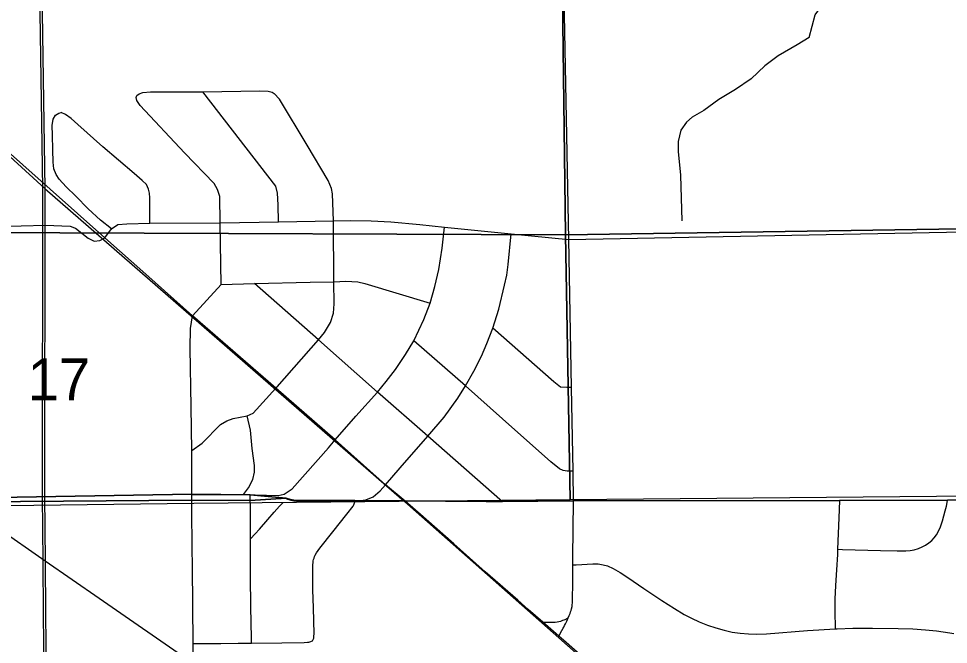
# Model space of a CAD drawing. Extents: x 0 to 40.2, y 0 to 22.
# Drawn here: x 4.597 to 5.526, y 17.276 to 17.901 of the extents above; entities that cross this region are included whole.
import ezdxf

# ---------------------------------------------------------------- set-up
doc = ezdxf.new("R2010")
doc.units = 0
for name, color, linetype in [('GM_X_City_Street', 7, 'Continuous'), ('GM_X_Corporation', 7, 'Continuous'), ('GM_X_Major_Lake', 7, 'Continuous'), ('GM_X_Major_Lake_Text', 7, 'Continuous'), ('GM_X_Major_River', 7, 'Continuous'), ('GM_X_Minor_Lake', 7, 'Continuous'), ('GM_X_Rail_Line', 7, 'Continuous'), ('GM_X_Unincorporated_Location', 7, 'Continuous')]:
    doc.layers.add(name, color=color, linetype=linetype)

msp = doc.modelspace()

# ---------------------------------------------------------------- linework, layer by layer
at = {"layer": 'GM_X_Corporation'}
for points in [[(5.1306, 18.69122), (6.13405, 18.70621), (6.1533, 17.70056), (5.14342, 17.68519)], [(5.1306, 18.69122), (5.14342, 17.68519), (4.13231, 17.68919), (4.11898, 18.68419)], [(6.1533, 17.70056), (6.15543, 17.42907), (5.77027, 17.42591), (5.14797, 17.42035), (5.14342, 17.68519)], [(5.14342, 17.68519), (5.14797, 17.42035), (4.77185, 17.41656), (4.13209, 17.4086), (4.13231, 17.68919)]]:
    msp.add_lwpolyline(points, close=True, dxfattribs=at)
for points in [[(4.12897, 17.41484), (4.76975, 17.42604), (4.82809, 17.4251), (4.8643, 17.42185), (4.86853, 17.42044), (4.87173, 17.41985), (4.87659, 17.41944), (4.88705, 17.4194), (4.91747, 17.41952), (4.93294, 17.41943), (4.98282, 17.41931), (5.0642, 17.41862), (5.08033, 17.4187), (5.15118, 17.41905), (5.41736, 17.41969), (5.5251, 17.41995), (5.58951, 17.42013), (5.59895, 17.42023), (5.60684, 17.42043), (5.61622, 17.42043), (5.63231, 17.42055), (6.1544, 17.42475), (6.56089, 17.42856)], [(6.56089, 17.42856), (6.1544, 17.42475), (5.63231, 17.42055), (5.61622, 17.42043), (5.60684, 17.42043), (5.59895, 17.42023), (5.58951, 17.42013), (5.5251, 17.41995), (5.41736, 17.41969), (5.15118, 17.41905), (5.08033, 17.4187), (5.0642, 17.41862), (4.98282, 17.41931), (4.93294, 17.41943), (4.91747, 17.41952), (4.88705, 17.4194), (4.87659, 17.41944), (4.87173, 17.41985), (4.86853, 17.42044), (4.8643, 17.42185), (4.82809, 17.4251), (4.76975, 17.42604), (4.12897, 17.41484)], [(6.56089, 17.42856), (6.1544, 17.42475), (5.63231, 17.42055), (5.61622, 17.42043), (5.60684, 17.42043), (5.59895, 17.42023), (5.58951, 17.42013), (5.5251, 17.41995), (5.41736, 17.41969), (5.15118, 17.41905), (5.0642, 17.41862), (4.98282, 17.41931), (4.93294, 17.41943), (4.91747, 17.41952), (4.88705, 17.4194), (4.87659, 17.41944), (4.87173, 17.41985), (4.86853, 17.42044), (4.8643, 17.42185), (4.8283, 17.41938), (4.76962, 17.4198), (4.12897, 17.41484)], [(4.12897, 17.41484), (4.76962, 17.4198), (4.8283, 17.41938), (4.8643, 17.42185), (4.86853, 17.42044), (4.87173, 17.41985), (4.87659, 17.41944), (4.88705, 17.4194), (4.91747, 17.41952), (4.93294, 17.41943), (4.98282, 17.41931), (5.0642, 17.41862), (5.15118, 17.41905), (5.41736, 17.41969), (5.5251, 17.41995), (5.58951, 17.42013), (5.59895, 17.42023), (5.60684, 17.42043), (5.61622, 17.42043), (5.63231, 17.42055), (6.1544, 17.42475), (6.56089, 17.42856)], [(6.56089, 17.42856), (6.1544, 17.42475), (5.63231, 17.42055), (5.61622, 17.42043), (5.60684, 17.42043), (5.59895, 17.42023), (5.58951, 17.42013), (5.5251, 17.41995), (5.41736, 17.41969), (5.15118, 17.41905), (5.08033, 17.4187), (5.0642, 17.41862), (4.98282, 17.41931), (4.93294, 17.41943), (4.91747, 17.41952), (4.88705, 17.4194), (4.87659, 17.41944), (4.87173, 17.41985), (4.86853, 17.42044), (4.8643, 17.42185), (4.82809, 17.4251), (4.76975, 17.42604), (4.12897, 17.41484)], [(4.12897, 17.41484), (4.76975, 17.42604), (4.82809, 17.4251), (4.8643, 17.42185), (4.86853, 17.42044), (4.87173, 17.41985), (4.87659, 17.41944), (4.88705, 17.4194), (4.91747, 17.41952), (4.93294, 17.41943), (4.98282, 17.41931), (5.0642, 17.41862), (5.08033, 17.4187), (5.15118, 17.41905), (5.41736, 17.41969), (5.5251, 17.41995), (5.58951, 17.42013), (5.59895, 17.42023), (5.60684, 17.42043), (5.61622, 17.42043), (5.63231, 17.42055), (6.1544, 17.42475), (6.56089, 17.42856)]]:
    msp.add_lwpolyline(points, dxfattribs=at)
at = {"layer": 'GM_X_Major_Lake'}
for points in [[(4.72382, 17.64572), (4.68301, 17.68221), (4.57325, 17.7794)], [(4.98304, 17.41876), (4.96348, 17.4352), (4.91301, 17.48009), (4.85393, 17.53179), (4.77045, 17.60402), (4.72382, 17.64572)], [(5.09568, 17.31984), (5.06325, 17.34832), (5.03165, 17.37638), (4.99837, 17.4054), (4.98304, 17.41876)], [(5.19169, 17.23518), (5.16328, 17.26059), (5.14142, 17.27994), (5.13684, 17.28392), (5.12082, 17.29787), (5.10624, 17.31056), (5.09568, 17.31984)]]:
    msp.add_lwpolyline(points, dxfattribs=at)
at = {"layer": 'GM_X_Major_Lake_Text'}
msp.add_line((5.14656, 17.68066), (5.137, 18.18327), dxfattribs=at)
for points in [[(4.09028, 17.68845), (4.1262, 17.68864), (4.1362, 17.68869), (4.25949, 17.68972), (4.37295, 17.69138), (4.46398, 17.69249), (4.48547, 17.69249), (4.53732, 17.69332), (4.56687, 17.69399), (4.5993, 17.69431), (4.62352, 17.69484), (4.64844, 17.69398), (4.65259, 17.69213)], [(4.68301, 17.68221), (4.68968, 17.6911), (4.69585, 17.69546), (4.70491, 17.69603), (4.72792, 17.69668), (4.79825, 17.69727), (4.85669, 17.69826), (4.91151, 17.69908), (4.92838, 17.69941), (4.94904, 17.699), (4.9688, 17.69801), (4.99785, 17.69546), (5.0223, 17.69287), (5.0892, 17.68626), (5.14656, 17.68066)], [(4.65259, 17.69213), (4.65363, 17.69167), (4.66639, 17.68179), (4.6724, 17.67867), (4.67783, 17.67965), (4.68301, 17.68221)], [(5.15141, 17.4185), (5.15117, 17.44883), (5.14952, 17.53243), (5.14656, 17.68066)], [(4.76998, 17.42548), (4.76998, 17.46955), (4.76917, 17.51332), (4.76837, 17.57181), (4.76844, 17.59165), (4.77045, 17.60402)], [(5.15066, 17.35511), (5.15057, 17.36291), (5.15141, 17.4185)], [(5.14611, 17.30224), (5.14716, 17.30467), (5.1479, 17.30662), (5.14853, 17.30825), (5.14897, 17.30949), (5.14953, 17.31137), (5.14998, 17.31355), (5.15012, 17.31478), (5.15038, 17.3177), (5.15052, 17.31953), (5.15051, 17.32113), (5.15051, 17.32274), (5.15051, 17.32457), (5.15063, 17.33322), (5.15076, 17.34713), (5.15066, 17.35511)], [(5.12082, 17.29787), (5.12499, 17.29775), (5.13021, 17.29788), (5.13203, 17.29794), (5.13317, 17.29801), (5.13492, 17.29819), (5.13681, 17.29851), (5.13863, 17.29895), (5.13943, 17.29924), (5.14021, 17.29952), (5.14086, 17.29978), (5.14217, 17.30032), (5.14297, 17.30065), (5.14611, 17.30224)], [(5.13684, 17.28392), (5.13985, 17.28954), (5.14112, 17.29193), (5.14172, 17.29304), (5.14244, 17.29441), (5.14347, 17.29637), (5.14474, 17.29904), (5.14611, 17.30224)]]:
    msp.add_lwpolyline(points, dxfattribs=at)
at = {"layer": 'GM_X_Major_River'}
for p, q in [((4.623, 17.73159), (4.97994, 17.42091)), ((4.54301, 17.4149), (4.62333, 17.35928))]:
    msp.add_line(p, q, dxfattribs=at)
for points in [[(4.62062, 17.42396), (4.6209, 17.73102), (4.61457, 18.14987), (4.61044, 19.18179), (4.60713, 19.57767), (4.60713, 19.63326), (4.61046, 19.67322), (4.61795, 19.71401)], [(4.62295, 17.42396), (4.62323, 17.73104), (4.6169, 18.1499), (4.61277, 19.18181), (4.60946, 19.57768), (4.60946, 19.63316), (4.61277, 19.67292), (4.62022, 19.7135)], [(4.623, 17.73159), (4.52561, 17.82001), (4.4278, 17.90731), (4.17647, 18.13451), (4.06677, 18.21824)], [(4.59498, 15.70159), (4.59656, 15.70372), (4.61052, 15.72266), (4.61811, 15.7396), (4.62426, 15.75717), (4.63093, 15.78112), (4.63373, 15.80092), (4.63465, 15.82821), (4.6339, 15.96965), (4.63233, 16.10669), (4.63064, 16.45685), (4.62545, 16.84695), (4.62537, 16.96937), (4.62178, 17.30668), (4.62122, 17.3587), (4.62062, 17.42396)], [(4.59686, 15.70021), (4.59843, 15.70234), (4.61254, 15.72149), (4.62028, 15.73875), (4.62648, 15.75648), (4.63322, 15.78065), (4.63606, 15.80072), (4.63698, 15.82818), (4.63623, 15.96967), (4.63466, 16.10671), (4.63297, 16.45687), (4.62777, 16.84697), (4.62769, 16.96938), (4.62411, 17.3067), (4.62355, 17.35873), (4.62295, 17.42396)], [(4.97994, 17.42091), (5.30245, 17.13578), (5.95038, 16.5554), (6.62714, 15.93274), (7.15702, 15.44764), (7.76806, 14.87866), (8.24495, 14.44186), (8.61841, 14.1)], [(4.62333, 17.35928), (4.67721, 17.32197), (4.76914, 17.2583), (4.77303, 16.83719)]]:
    msp.add_lwpolyline(points, dxfattribs=at)
at = {"layer": 'GM_X_Minor_Lake'}
for points in [[(5.38688, 17.88245), (5.39001, 17.8938), (5.39276, 17.90516), (5.4035, 17.92023), (5.41194, 17.93343), (5.42123, 17.95611), (5.42217, 17.9762), (5.42117, 17.99063), (5.42501, 17.99704), (5.43046, 18.01255), (5.4298, 18.02317), (5.42952, 18.0338), (5.4315, 18.04402), (5.43575, 18.05347), (5.43737, 18.06483), (5.44013, 18.07657), (5.44328, 18.0902), (5.44756, 18.10268), (5.45976, 18.11319), (5.46588, 18.12034), (5.47465, 18.12746), (5.48037, 18.13234), (5.48574, 18.13988), (5.48957, 18.14592)], [(5.38688, 17.88245), (5.37508, 17.87497), (5.35606, 17.86415), (5.34273, 17.85403), (5.32899, 17.84126), (5.31338, 17.8304), (5.29664, 17.82031), (5.28179, 17.80945), (5.26999, 17.80273), (5.26427, 17.79785), (5.25853, 17.78993), (5.25615, 17.77857), (5.25605, 17.76833), (5.25849, 17.74479), (5.25958, 17.69926)]]:
    msp.add_lwpolyline(points, dxfattribs=at)
at = {"layer": 'GM_X_Rail_Line'}
for points in [[(4.77126, 17.27642), (4.77055, 17.3533), (4.77038, 17.37255), (4.76983, 17.40978), (4.76998, 17.42548)], [(5.15066, 17.35511), (5.15414, 17.35532), (5.1706, 17.35632), (5.17592, 17.35607), (5.181, 17.35533), (5.18544, 17.35407), (5.19097, 17.35144), (5.19793, 17.34744), (5.20577, 17.34245), (5.22172, 17.33166), (5.2398, 17.3195), (5.25243, 17.3115), (5.26206, 17.30572), (5.26921, 17.30187), (5.27715, 17.29815), (5.28528, 17.2949), (5.29358, 17.2921), (5.30202, 17.28977), (5.30998, 17.28806), (5.31803, 17.28682), (5.32614, 17.28609), (5.33428, 17.28591), (5.34426, 17.28629), (5.3852, 17.28947), (5.41327, 17.29118)], [(5.41327, 17.29118), (5.41497, 17.29129), (5.43048, 17.2918), (5.45036, 17.29192), (5.47582, 17.2917), (5.4907, 17.29118), (5.50305, 17.29028), (5.51415, 17.28907), (5.52764, 17.28711), (5.53163, 17.28641)], [(4.77188, 17.22524), (4.77148, 17.25458), (4.77126, 17.27642)]]:
    msp.add_lwpolyline(points, dxfattribs=at)
at = {"layer": 'GM_X_Unincorporated_Location'}
for points in [[(4.71511, 17.82448), (4.71727, 17.82629), (4.72086, 17.82761), (4.72873, 17.82798), (4.78089, 17.8282), (4.83784, 17.82908), (4.84611, 17.82889), (4.85013, 17.82772), (4.85233, 17.82658)], [(4.85669, 17.69826), (4.85614, 17.71506), (4.8554, 17.72678), (4.85372, 17.73366), (4.78089, 17.8282)], [(4.85526, 17.53331), (4.89661, 17.58022), (4.90245, 17.58738), (4.90838, 17.59759), (4.91159, 17.60697), (4.91217, 17.61603), (4.91191, 17.63815), (4.91151, 17.69908), (4.9106, 17.726), (4.90945, 17.73159), (4.90624, 17.73958), (4.88533, 17.77489), (4.85768, 17.8209), (4.85233, 17.82658)], [(4.77045, 17.60402), (4.79928, 17.6356), (4.79825, 17.69727), (4.7979, 17.72345), (4.79567, 17.7304), (4.79226, 17.73657), (4.76274, 17.76727), (4.71839, 17.81437), (4.71479, 17.81945), (4.71427, 17.82249), (4.71511, 17.82448)], [(4.68968, 17.6911), (4.67852, 17.6998), (4.66625, 17.7113), (4.65392, 17.7237), (4.64444, 17.73326), (4.63741, 17.74094), (4.63423, 17.74537), (4.63207, 17.75115), (4.63123, 17.75785), (4.63093, 17.77022), (4.63057, 17.78497), (4.63042, 17.79445), (4.63123, 17.80075), (4.63357, 17.80496), (4.63683, 17.80693), (4.63917, 17.80733)], [(4.72792, 17.69668), (4.72796, 17.72231), (4.72752, 17.72674), (4.72657, 17.73091), (4.72456, 17.73541), (4.72039, 17.7394), (4.71226, 17.74647), (4.68104, 17.7733), (4.65582, 17.79533), (4.64938, 17.80148), (4.64364, 17.80561), (4.63917, 17.80733)], [(5.14656, 17.68066), (5.60992, 17.68952), (5.61291, 17.68958), (5.61798, 17.6897), (5.82615, 17.69451), (5.98519, 17.69809), (6.06403, 17.69944), (6.14544, 17.70075), (6.41974, 17.70708), (6.66088, 17.71027), (7.14766, 17.71966), (7.44219, 17.72601), (7.72193, 17.73118), (7.94375, 17.73546), (8.02286, 17.73868), (8.16105, 17.73241), (8.9, 17.74624)], [(4.76998, 17.42548), (4.82144, 17.42541), (4.85614, 17.42446), (4.86229, 17.426), (4.87012, 17.43134), (4.9065, 17.47233), (4.91301, 17.48009), (4.93395, 17.50374), (4.95562, 17.52796), (4.96403, 17.53858), (4.97355, 17.55058), (4.98343, 17.56544), (4.99178, 17.5792), (5.00188, 17.60051), (5.0081, 17.61698), (5.01286, 17.63359), (5.01689, 17.65036), (5.02025, 17.6718), (5.0223, 17.69287)], [(4.93317, 17.41887), (4.94368, 17.42007), (4.95122, 17.42307), (4.95818, 17.42936), (4.96348, 17.4352), (4.97816, 17.45206), (5.00583, 17.48397), (5.02208, 17.503), (5.0357, 17.52182), (5.04331, 17.53404), (5.0518, 17.54897), (5.05941, 17.56369), (5.06483, 17.57635), (5.0709, 17.5919), (5.07684, 17.6109), (5.08233, 17.63491), (5.08474, 17.64472), (5.08621, 17.65548), (5.0892, 17.68626)], [(4.79928, 17.6356), (4.83271, 17.63663), (4.88813, 17.63789), (4.91191, 17.63815), (4.92399, 17.63868), (4.93578, 17.63817), (4.94295, 17.63663), (5.0081, 17.61698)], [(5.08056, 17.41815), (5.00583, 17.48397), (4.95562, 17.52796), (4.89661, 17.58022), (4.83271, 17.63663)], [(5.14952, 17.53243), (5.14462, 17.53243), (5.13847, 17.53302), (5.13159, 17.53821), (5.0709, 17.5919)], [(5.15117, 17.44883), (5.14513, 17.44883), (5.14103, 17.44964), (5.13745, 17.45125), (5.12888, 17.45828), (5.08042, 17.50132), (5.04331, 17.53404), (4.99178, 17.5792)], [(4.81815, 17.50289), (4.8251, 17.50417), (4.83132, 17.50696), (4.85393, 17.53179), (4.85526, 17.53331)], [(4.76998, 17.46955), (4.78015, 17.47672), (4.79867, 17.49539), (4.80482, 17.49934), (4.81119, 17.50161), (4.81815, 17.50289)], [(4.82144, 17.42541), (4.82656, 17.43222), (4.83096, 17.44056), (4.83271, 17.44781), (4.83249, 17.45447), (4.8303, 17.47145), (4.82839, 17.48983), (4.8251, 17.50417)], [(4.82952, 17.27697), (4.82944, 17.28196), (4.82895, 17.31334), (4.82863, 17.34357), (4.82857, 17.38111), (4.82857, 17.38262), (4.82855, 17.39567), (4.82857, 17.40909), (4.82832, 17.42455)], [(4.82857, 17.38111), (4.83313, 17.38611), (4.83761, 17.39102), (4.84572, 17.4004), (4.85217, 17.40792), (4.85757, 17.4139), (4.86105, 17.41759)], [(4.86453, 17.42129), (4.86875, 17.41989), (4.87195, 17.4193), (4.87682, 17.41889), (4.88728, 17.41884), (4.9177, 17.41897), (4.93317, 17.41887)], [(4.89045, 17.27937), (4.89092, 17.27992), (4.89127, 17.28048), (4.89155, 17.28114), (4.89173, 17.28183), (4.89189, 17.28283), (4.89198, 17.28388), (4.89206, 17.28616), (4.89145, 17.31225), (4.89099, 17.33022), (4.89076, 17.35067), (4.89076, 17.35289), (4.89081, 17.35553), (4.89102, 17.3573), (4.89127, 17.35917), (4.89161, 17.36069), (4.89203, 17.36205), (4.89254, 17.36341), (4.89322, 17.36475), (4.89466, 17.36723), (4.89611, 17.36953), (4.89786, 17.37186), (4.91096, 17.38835), (4.92486, 17.40587), (4.931, 17.41397), (4.93175, 17.41515), (4.93223, 17.41622), (4.93317, 17.41887)], [(5.41327, 17.29118), (5.41315, 17.29553), (5.41291, 17.30481), (5.4129, 17.31496), (5.41296, 17.32082), (5.41367, 17.33453), (5.41474, 17.35006), (5.41552, 17.3656), (5.41571, 17.37076), (5.41693, 17.40233), (5.41759, 17.41913)], [(5.41571, 17.37076), (5.42031, 17.37064), (5.4581, 17.36967), (5.47485, 17.36913), (5.48351, 17.36921), (5.48777, 17.36956), (5.49196, 17.3703), (5.49605, 17.37146), (5.49998, 17.37307), (5.50318, 17.37478), (5.50668, 17.37719), (5.50942, 17.37957), (5.5119, 17.38222), (5.51409, 17.38512), (5.51622, 17.38878), (5.51818, 17.39323), (5.52014, 17.39906), (5.52289, 17.40922), (5.52403, 17.41393), (5.52533, 17.4194)], [(4.77126, 17.27642), (4.799, 17.27657), (4.81638, 17.27681), (4.82952, 17.27697), (4.85994, 17.27734), (4.88221, 17.27767), (4.88543, 17.27787), (4.88702, 17.27806), (4.88802, 17.27826), (4.88887, 17.27851), (4.88951, 17.27875), (4.89045, 17.27937)]]:
    msp.add_lwpolyline(points, dxfattribs=at)

# ---------------------------------------------------------------- texts
at = {"layer": 'GM_X_City_Street'}
msp.add_text('17', height=0.041856, rotation=0.00001, dxfattribs=at).set_placement((4.60593, 17.51976))

doc.saveas('drawing.dxf')
